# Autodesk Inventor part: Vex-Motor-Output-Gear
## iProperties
Created: 2007-08
Part Number: Vex-Motor-Output-Gear
Document SubType Name: Modeling
Density: 1 g/cm^3
Mass: 0.82152 g
Surface Area: 15.4192 cm^2
Volume: 0.82152 cm^3
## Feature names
1. Base1
